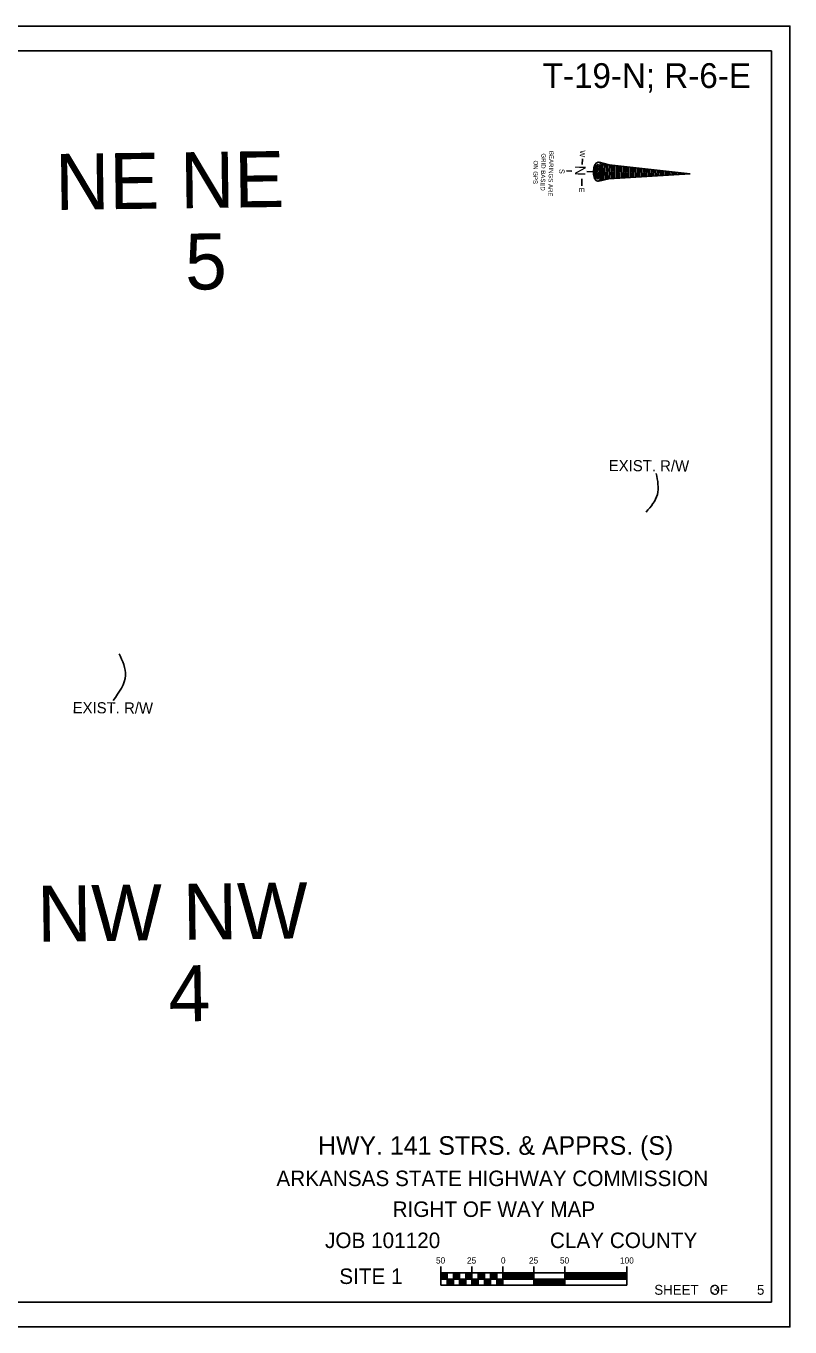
# Model space of a CAD drawing. Extents: x -5566 to 1759129, y -3726 to 731467.
# Drawn here: x 1034 to 1650, y 0 to 1050 of the extents above; entities that cross this region are included whole.
import ezdxf

# ---------------------------------------------------------------- set-up
doc = ezdxf.new("R2010")
doc.units = 0
for name, color, linetype in [('Default', 7, 'Continuous'), ('E_Label', 7, 'Continuous'), ('R_No Plot', 7, 'Continuous')]:
    doc.layers.add(name, color=color, linetype=linetype)

msp = doc.modelspace()

# ---------------------------------------------------------------- linework, layer by layer
at = {"layer": 'Default'}
for p, q in [((55, 1030), (1635, 1030)), ((1635, 1030), (1635, 20)), ((1482.6, 942.9), (1482.5, 938.3)), ((1504.2, 938), (1496.1, 940)), ((1496.2, 940), (1496.2, 940)), ((1497.5, 939.6), (1497.5, 938.8)), ((1499, 939.3), (1498.9, 935.3)), ((1500.4, 938.9), (1500, 925.8)), ((1501.8, 938.6), (1501.5, 926.1)), ((1503.2, 938.2), (1502.9, 926.4)), ((1569.6, 930.6), (1504.2, 938)), ((1504.6, 937.9), (1504.3, 926.7)), ((1506, 937.8), (1505.7, 926.8)), ((1507.4, 937.6), (1507.2, 926.8)), ((1508.8, 937.4), (1508.6, 926.9)), ((1510.3, 937.3), (1510, 927)), ((1511.7, 937.1), (1511.4, 927.1)), ((1513.1, 937), (1512.8, 927.2)), ((1514.5, 936.8), (1514.3, 927.3)), ((1515.9, 936.6), (1515.7, 927.4)), ((1517.3, 936.5), (1517.1, 927.4)), ((1518.7, 936.3), (1518.5, 927.5)), ((1520.1, 936.2), (1519.9, 927.6)), ((1521.6, 936), (1521.4, 927.7)), ((1523, 935.8), (1522.8, 927.8)), ((1524.4, 935.7), (1524.2, 927.9)), ((1525.8, 935.5), (1525.6, 928)), ((1527.2, 935.4), (1527, 928)), ((1528.6, 935.2), (1528.5, 928.1)), ((1530, 935.1), (1529.9, 928.2)), ((1531.5, 934.9), (1531.3, 928.3)), ((1532.9, 934.7), (1532.7, 928.4)), ((1534.3, 934.6), (1534.1, 928.5)), ((1469.7, 933), (1474.2, 932.9)), ((1482.2, 926.7), (1482.1, 921)), ((1486.1, 932.6), (1495.3, 932.4)), ((1503.9, 926.6), (1495.9, 924.8)), ((1497.2, 925.9), (1497.2, 925.1)), ((1498.7, 929.4), (1498.6, 925.5)), ((1569.6, 930.6), (1503.9, 926.6)), ((1535.7, 934.4), (1535.6, 928.6)), ((1537.1, 934.3), (1537, 928.6)), ((1538.5, 934.1), (1538.4, 928.7)), ((1539.9, 933.9), (1539.8, 928.8)), ((1541.4, 933.8), (1541.2, 928.9)), ((1542.8, 933.6), (1542.7, 929)), ((1544.2, 933.5), (1544.1, 929.1)), ((1545.6, 933.3), (1545.5, 929.2)), ((1547, 933.1), (1546.9, 929.2)), ((1548.4, 933), (1548.3, 929.3)), ((1549.8, 932.8), (1549.8, 929.4)), ((1551.3, 932.7), (1551.2, 929.5)), ((1552.7, 932.5), (1552.6, 929.6)), ((1554.1, 932.4), (1554, 929.7)), ((1555.5, 932.2), (1555.4, 929.7)), ((1556.9, 932), (1556.9, 929.8)), ((1558.3, 931.9), (1558.3, 929.9)), ((1559.7, 931.7), (1559.7, 930)), ((1561.1, 931.6), (1561.1, 930.1)), ((1562.6, 931.4), (1562.5, 930.2)), ((1564, 931.2), (1564, 930.3)), ((1565.4, 931.1), (1565.4, 930.3)), ((1566.8, 930.9), (1566.8, 930.4)), ((1568.2, 930.8), (1568.2, 930.5)), ((1569.6, 930.6), (1569.6, 930.6)), ((1368.5, 48.7), (1368.5, 33.7)), ((1518.5, 43.7), (1368.5, 43.7)), ((1368.5, 43.4), (1373.5, 43.4)), ((1368.5, 43.2), (1373.5, 43.2)), ((1368.5, 42.9), (1373.5, 42.9)), ((1368.5, 42.7), (1373.5, 42.7)), ((1368.5, 42.4), (1373.5, 42.4)), ((1368.5, 42.2), (1373.5, 42.2)), ((1373.5, 43.7), (1373.5, 33.7)), ((1378.5, 43.7), (1378.5, 33.7)), ((1378.5, 43.4), (1383.5, 43.4)), ((1378.5, 43.2), (1383.5, 43.2)), ((1378.5, 42.9), (1383.5, 42.9)), ((1378.5, 42.7), (1383.5, 42.7)), ((1378.5, 42.4), (1383.5, 42.4)), ((1378.5, 42.2), (1383.5, 42.2)), ((1383.5, 43.7), (1383.5, 33.7)), ((1388.5, 43.7), (1388.5, 33.7)), ((1388.5, 43.4), (1393.5, 43.4)), ((1388.5, 43.2), (1393.5, 43.2)), ((1388.5, 42.9), (1393.5, 42.9)), ((1388.5, 42.7), (1393.5, 42.7)), ((1388.5, 42.4), (1393.5, 42.4)), ((1388.5, 42.2), (1393.5, 42.2)), ((1393.5, 48.7), (1393.5, 33.7)), ((1398.5, 43.7), (1398.5, 33.7)), ((1398.5, 43.4), (1403.5, 43.4)), ((1398.5, 43.2), (1403.5, 43.2)), ((1398.5, 42.9), (1403.5, 42.9)), ((1398.5, 42.7), (1403.5, 42.7)), ((1398.5, 42.4), (1403.5, 42.4)), ((1398.5, 42.2), (1403.5, 42.2)), ((1403.5, 43.7), (1403.5, 33.7)), ((1408.5, 43.7), (1408.5, 33.7)), ((1408.5, 43.4), (1413.5, 43.4)), ((1408.5, 43.2), (1413.5, 43.2)), ((1408.5, 42.9), (1413.5, 42.9)), ((1408.5, 42.7), (1413.5, 42.7)), ((1408.5, 42.4), (1413.5, 42.4)), ((1408.5, 42.2), (1413.5, 42.2)), ((1413.5, 43.7), (1413.5, 33.7)), ((1418.5, 48.7), (1418.5, 33.7)), ((1443.5, 43.4), (1418.5, 43.4)), ((1443.5, 43.2), (1418.5, 43.2)), ((1443.5, 42.9), (1418.5, 42.9)), ((1443.5, 42.7), (1418.5, 42.7)), ((1443.5, 42.4), (1418.5, 42.4)), ((1443.5, 42.2), (1418.5, 42.2)), ((1443.5, 48.7), (1443.5, 33.7)), ((1468.5, 43.4), (1518.5, 43.4)), ((1468.5, 43.2), (1518.5, 43.2)), ((1468.5, 42.9), (1518.5, 42.9)), ((1468.5, 42.7), (1518.5, 42.7)), ((1468.5, 42.4), (1518.5, 42.4)), ((1468.5, 42.2), (1518.5, 42.2)), ((1468.5, 48.7), (1468.5, 33.7)), ((1518.5, 48.7), (1518.5, 33.7)), ((1368.5, 41.9), (1373.5, 41.9)), ((1368.5, 41.7), (1373.5, 41.7)), ((1368.5, 41.4), (1373.5, 41.4)), ((1368.5, 41.2), (1373.5, 41.2)), ((1368.5, 40.9), (1373.5, 40.9)), ((1368.5, 40.7), (1373.5, 40.7)), ((1368.5, 40.4), (1373.5, 40.4)), ((1368.5, 40.2), (1373.5, 40.2)), ((1368.5, 39.9), (1373.5, 39.9)), ((1368.5, 39.7), (1373.5, 39.7)), ((1368.5, 39.4), (1373.5, 39.4)), ((1368.5, 39.2), (1373.5, 39.2)), ((1368.5, 38.9), (1373.5, 38.9)), ((1518.5, 38.7), (1368.5, 38.7)), ((1518.5, 33.7), (1368.5, 33.7)), ((1373.5, 38.4), (1378.5, 38.4)), ((1373.5, 38.2), (1378.5, 38.2)), ((1373.5, 37.9), (1378.5, 37.9)), ((1373.5, 37.7), (1378.5, 37.7)), ((1373.5, 37.4), (1378.5, 37.4)), ((1373.5, 37.2), (1378.5, 37.2)), ((1373.5, 36.9), (1378.5, 36.9)), ((1373.5, 36.7), (1378.5, 36.7)), ((1373.5, 36.4), (1378.5, 36.4)), ((1373.5, 36.2), (1378.5, 36.2)), ((1373.5, 35.9), (1378.5, 35.9)), ((1373.5, 35.7), (1378.5, 35.7)), ((1373.5, 35.4), (1378.5, 35.4)), ((1373.5, 35.2), (1378.5, 35.2)), ((1373.5, 34.9), (1378.5, 34.9)), ((1373.5, 34.7), (1378.5, 34.7)), ((1373.5, 34.4), (1378.5, 34.4)), ((1373.5, 34.2), (1378.5, 34.2)), ((1373.5, 33.9), (1378.5, 33.9)), ((1378.5, 41.9), (1383.5, 41.9)), ((1378.5, 41.7), (1383.5, 41.7)), ((1378.5, 41.4), (1383.5, 41.4)), ((1378.5, 41.2), (1383.5, 41.2)), ((1378.5, 40.9), (1383.5, 40.9)), ((1378.5, 40.7), (1383.5, 40.7)), ((1378.5, 40.4), (1383.5, 40.4)), ((1378.5, 40.2), (1383.5, 40.2)), ((1378.5, 39.9), (1383.5, 39.9)), ((1378.5, 39.7), (1383.5, 39.7)), ((1378.5, 39.4), (1383.5, 39.4)), ((1378.5, 39.2), (1383.5, 39.2)), ((1378.5, 38.9), (1383.5, 38.9)), ((1383.5, 38.4), (1388.5, 38.4)), ((1383.5, 38.2), (1388.5, 38.2)), ((1383.5, 37.9), (1388.5, 37.9)), ((1383.5, 37.7), (1388.5, 37.7)), ((1383.5, 37.4), (1388.5, 37.4)), ((1383.5, 37.2), (1388.5, 37.2)), ((1383.5, 36.9), (1388.5, 36.9)), ((1383.5, 36.7), (1388.5, 36.7)), ((1383.5, 36.4), (1388.5, 36.4)), ((1383.5, 36.2), (1388.5, 36.2)), ((1383.5, 35.9), (1388.5, 35.9)), ((1383.5, 35.7), (1388.5, 35.7)), ((1383.5, 35.4), (1388.5, 35.4)), ((1383.5, 35.2), (1388.5, 35.2)), ((1383.5, 34.9), (1388.5, 34.9)), ((1383.5, 34.7), (1388.5, 34.7)), ((1383.5, 34.4), (1388.5, 34.4)), ((1383.5, 34.2), (1388.5, 34.2)), ((1383.5, 33.9), (1388.5, 33.9)), ((1388.5, 41.9), (1393.5, 41.9)), ((1388.5, 41.7), (1393.5, 41.7)), ((1388.5, 41.4), (1393.5, 41.4)), ((1388.5, 41.2), (1393.5, 41.2)), ((1388.5, 40.9), (1393.5, 40.9)), ((1388.5, 40.7), (1393.5, 40.7)), ((1388.5, 40.4), (1393.5, 40.4)), ((1388.5, 40.2), (1393.5, 40.2)), ((1388.5, 39.9), (1393.5, 39.9)), ((1388.5, 39.7), (1393.5, 39.7)), ((1388.5, 39.4), (1393.5, 39.4)), ((1388.5, 39.2), (1393.5, 39.2)), ((1388.5, 38.9), (1393.5, 38.9)), ((1393.5, 38.4), (1398.5, 38.4)), ((1393.5, 38.2), (1398.5, 38.2)), ((1393.5, 37.9), (1398.5, 37.9)), ((1393.5, 37.7), (1398.5, 37.7)), ((1393.5, 37.4), (1398.5, 37.4)), ((1393.5, 37.2), (1398.5, 37.2)), ((1393.5, 36.9), (1398.5, 36.9)), ((1393.5, 36.7), (1398.5, 36.7)), ((1393.5, 36.4), (1398.5, 36.4)), ((1393.5, 36.2), (1398.5, 36.2)), ((1393.5, 35.9), (1398.5, 35.9)), ((1393.5, 35.7), (1398.5, 35.7)), ((1393.5, 35.4), (1398.5, 35.4)), ((1393.5, 35.2), (1398.5, 35.2)), ((1393.5, 34.9), (1398.5, 34.9)), ((1393.5, 34.7), (1398.5, 34.7)), ((1393.5, 34.4), (1398.5, 34.4)), ((1393.5, 34.2), (1398.5, 34.2)), ((1393.5, 33.9), (1398.5, 33.9)), ((1398.5, 41.9), (1403.5, 41.9)), ((1398.5, 41.7), (1403.5, 41.7)), ((1398.5, 41.4), (1403.5, 41.4)), ((1398.5, 41.2), (1403.5, 41.2)), ((1398.5, 40.9), (1403.5, 40.9)), ((1398.5, 40.7), (1403.5, 40.7)), ((1398.5, 40.4), (1403.5, 40.4)), ((1398.5, 40.2), (1403.5, 40.2)), ((1398.5, 39.9), (1403.5, 39.9)), ((1398.5, 39.7), (1403.5, 39.7)), ((1398.5, 39.4), (1403.5, 39.4)), ((1398.5, 39.2), (1403.5, 39.2)), ((1398.5, 38.9), (1403.5, 38.9)), ((1403.5, 38.4), (1408.5, 38.4)), ((1403.5, 38.2), (1408.5, 38.2)), ((1403.5, 37.9), (1408.5, 37.9)), ((1403.5, 37.7), (1408.5, 37.7)), ((1403.5, 37.4), (1408.5, 37.4)), ((1403.5, 37.2), (1408.5, 37.2)), ((1403.5, 36.9), (1408.5, 36.9)), ((1403.5, 36.7), (1408.5, 36.7)), ((1403.5, 36.4), (1408.5, 36.4)), ((1403.5, 36.2), (1408.5, 36.2)), ((1403.5, 35.9), (1408.5, 35.9)), ((1403.5, 35.7), (1408.5, 35.7)), ((1403.5, 35.4), (1408.5, 35.4)), ((1403.5, 35.2), (1408.5, 35.2)), ((1403.5, 34.9), (1408.5, 34.9)), ((1403.5, 34.7), (1408.5, 34.7)), ((1403.5, 34.4), (1408.5, 34.4)), ((1403.5, 34.2), (1408.5, 34.2)), ((1403.5, 33.9), (1408.5, 33.9)), ((1408.5, 41.9), (1413.5, 41.9)), ((1408.5, 41.7), (1413.5, 41.7)), ((1408.5, 41.4), (1413.5, 41.4)), ((1408.5, 41.2), (1413.5, 41.2)), ((1408.5, 40.9), (1413.5, 40.9)), ((1408.5, 40.7), (1413.5, 40.7)), ((1408.5, 40.4), (1413.5, 40.4)), ((1408.5, 40.2), (1413.5, 40.2)), ((1408.5, 39.9), (1413.5, 39.9)), ((1408.5, 39.7), (1413.5, 39.7)), ((1408.5, 39.4), (1413.5, 39.4)), ((1408.5, 39.2), (1413.5, 39.2)), ((1408.5, 38.9), (1413.5, 38.9)), ((1413.5, 38.4), (1418.5, 38.4)), ((1413.5, 38.2), (1418.5, 38.2)), ((1413.5, 37.9), (1418.5, 37.9)), ((1413.5, 37.7), (1418.5, 37.7)), ((1413.5, 37.4), (1418.5, 37.4)), ((1413.5, 37.2), (1418.5, 37.2)), ((1413.5, 36.9), (1418.5, 36.9)), ((1413.5, 36.7), (1418.5, 36.7)), ((1413.5, 36.4), (1418.5, 36.4)), ((1413.5, 36.2), (1418.5, 36.2)), ((1413.5, 35.9), (1418.5, 35.9)), ((1413.5, 35.7), (1418.5, 35.7)), ((1413.5, 35.4), (1418.5, 35.4)), ((1413.5, 35.2), (1418.5, 35.2)), ((1413.5, 34.9), (1418.5, 34.9)), ((1413.5, 34.7), (1418.5, 34.7)), ((1413.5, 34.4), (1418.5, 34.4)), ((1413.5, 34.2), (1418.5, 34.2)), ((1413.5, 33.9), (1418.5, 33.9)), ((1443.5, 41.9), (1418.5, 41.9)), ((1443.5, 41.7), (1418.5, 41.7)), ((1443.5, 41.4), (1418.5, 41.4)), ((1443.5, 41.2), (1418.5, 41.2)), ((1443.5, 40.9), (1418.5, 40.9)), ((1443.5, 40.7), (1418.5, 40.7)), ((1443.5, 40.4), (1418.5, 40.4)), ((1443.5, 40.2), (1418.5, 40.2)), ((1443.5, 39.9), (1418.5, 39.9)), ((1443.5, 39.7), (1418.5, 39.7)), ((1443.5, 39.4), (1418.5, 39.4)), ((1443.5, 39.2), (1418.5, 39.2)), ((1443.5, 38.9), (1418.5, 38.9)), ((1468.5, 38.4), (1443.5, 38.4)), ((1468.5, 38.2), (1443.5, 38.2)), ((1468.5, 37.9), (1443.5, 37.9)), ((1468.5, 37.7), (1443.5, 37.7)), ((1468.5, 37.4), (1443.5, 37.4)), ((1468.5, 37.2), (1443.5, 37.2)), ((1468.5, 36.9), (1443.5, 36.9)), ((1468.5, 36.7), (1443.5, 36.7)), ((1468.5, 36.4), (1443.5, 36.4)), ((1468.5, 36.2), (1443.5, 36.2)), ((1468.5, 35.9), (1443.5, 35.9)), ((1468.5, 35.7), (1443.5, 35.7)), ((1468.5, 35.4), (1443.5, 35.4)), ((1468.5, 35.2), (1443.5, 35.2)), ((1468.5, 34.9), (1443.5, 34.9)), ((1468.5, 34.7), (1443.5, 34.7)), ((1468.5, 34.4), (1443.5, 34.4)), ((1468.5, 34.2), (1443.5, 34.2)), ((1468.5, 33.9), (1443.5, 33.9)), ((1468.5, 41.9), (1518.5, 41.9)), ((1468.5, 41.7), (1518.5, 41.7)), ((1468.5, 41.4), (1518.5, 41.4)), ((1468.5, 41.2), (1518.5, 41.2)), ((1468.5, 40.9), (1518.5, 40.9)), ((1468.5, 40.7), (1518.5, 40.7)), ((1468.5, 40.4), (1518.5, 40.4)), ((1468.5, 40.2), (1518.5, 40.2)), ((1468.5, 39.9), (1518.5, 39.9)), ((1468.5, 39.7), (1518.5, 39.7)), ((1468.5, 39.4), (1518.5, 39.4)), ((1468.5, 39.2), (1518.5, 39.2)), ((1468.5, 38.9), (1518.5, 38.9)), ((1635, 20), (55, 20))]:
    msp.add_line(p, q, dxfattribs=at)
msp.add_lwpolyline([(0, 0), (1650, 0), (1650, 1050), (0, 1050)], close=True, dxfattribs=at)
msp.add_lwpolyline([(0, 0), (1650, 0), (1650, 1050), (0, 1050)], close=True, dxfattribs=at)
msp.add_lwpolyline([(1504.6, 937.9), (1504.7, 937.9)], dxfattribs=at)
msp.add_ellipse((1495.3, 932.4), major_axis=(-0.19, -7.72), ratio=0.492084, start_param=2.584597, end_param=7.472523, dxfattribs=at)
for major_axis in [(0.19, 7.72), (0.14, 5.79), (0.11, 4.62), (0.08, 3.47), (0.06, 2.6), (0.05, 1.95)]:
    msp.add_ellipse((1495.3, 932.4), major_axis=major_axis, ratio=0.492106, dxfattribs=at)
for points in [[(1534, 657.7), (1543.1, 671.9), (1542.1, 688.9)], [(1108.9, 543.4), (1114.1, 525.9), (1104.2, 505.7)]]:
    msp.add_spline(points, degree=3, dxfattribs=at)
at = {"layer": 'R_No Plot'}
msp.add_lwpolyline([(0, 0), (1650, 0), (1650, 1050), (0, 1050)], close=True, dxfattribs=at)

# ---------------------------------------------------------------- texts
at = {"layer": 'Default'}
for s, height, rotation, p in [('T-19-N; R-6-E', 20, 360, (1450.6, 1000)), (' NE NE', 45.2, 0.7646, (1040.9, 901.3)), ('GRID BASED', 3.54, 268.6002, (1449.6, 947.2)), ('BEARINGS ARE', 3.543, 268.6002, (1455.9, 949.2)), ('W', 4.25, 268.6002, (1480.6, 949.7)), ('ON GPS', 3.54, 268.6002, (1443.3, 941.5)), ('N', 8.5, 268.6002, (1476.7, 937.5)), ('S', 4.25, 268.6002, (1464, 934.7)), ('E', 4.25, 268.6002, (1479.9, 919.6)), ('5', 45.2, 0.7646, (1162.4, 837.2)), (' NW NW', 45.2, 0.7646, (1026.4, 310.6)), ('4', 45.2, 0.7646, (1149.1, 246.5)), ('HWY. 141 STRS. & APPRS. (S)', 15, 360, (1269.4, 139)), ('ARKANSAS STATE HIGHWAY COMMISSION', 12.5, 360, (1235.8, 113.7)), ('RIGHT OF WAY MAP', 12.5, 360, (1329.5, 88.8)), ('JOB 101120', 12.5, 360, (1275, 63.7)), ('CLAY COUNTY', 12.5, 360, (1456.4, 63.7)), ('50', 5, 360, (1364.5, 51.2)), ('25', 5, 360, (1389.5, 51.2)), ('0', 5, 360, (1416.9, 51.2)), ('25', 5, 360, (1439.5, 51.2)), ('50', 5, 360, (1464.5, 51.2)), ('100', 5, 360, (1512.9, 51.2)), ('SITE 1', 12.5, 360, (1286.5, 34.7)), ('SHEET   OF', 8, 360, (1540.6, 26)), ('3', 8, 360, (1586.7, 26)), ('5', 8, 360, (1623.4, 26))]:
    msp.add_text(s, height=height, rotation=rotation, dxfattribs=at).set_placement(p)
at = {"layer": 'E_Label'}
for p in [(1503.8, 690.8), (1071.4, 495.4)]:
    msp.add_text('EXIST. R/W', height=9, rotation=359.6555, dxfattribs=at).set_placement(p)

doc.saveas('drawing.dxf')
